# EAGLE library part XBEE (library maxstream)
XBee (TM) /XBee-PRO(TM) OEM RF Modules Source: MaxStream, Inc. xbee_productmanual.pdf
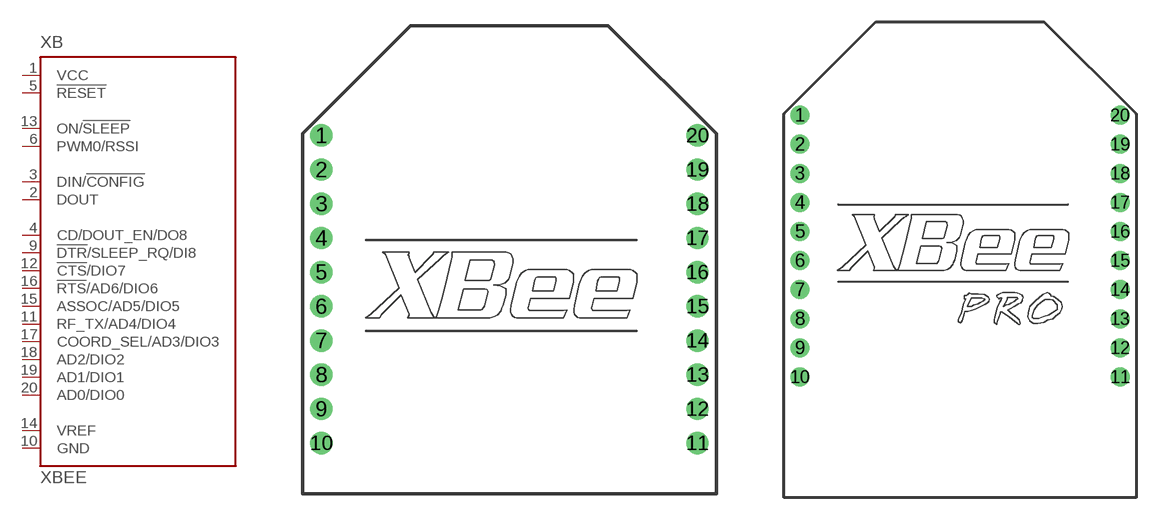
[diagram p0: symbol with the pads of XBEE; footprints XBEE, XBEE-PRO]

Designator prefix XB

## XBEE (MPN: XBP24-Z7UIT-004; OC_FARNELL: 1751799; OC_NEWARK: 34R5507)  [XBEE]
1  VCC  pwr
2  DOUT  out
3  DIN/!CONFIG  in
4  CD/DOUT_EN/DO8  out
5  !RESET  in
6  PWM0/RSSI  out
9  !DTR!/SLEEP_RQ/DI8
10  GND  pwr
11  RF_TX/AD4/DIO4
12  !CTS!/DIO7
13  ON/!SLEEP  out
14  VREF  in
15  ASSOC/AD5/DIO5
16  !RTS!/AD6/DIO6
17  COORD_SEL/AD3/DIO3
18  AD2/DIO2
19  AD1/DIO1
20  AD0/DIO0

## XBEE-PRO (MPN: XBP24-AWI-001; OC_FARNELL: 1337916; OC_NEWARK: 42M2667)  [XBEE-PRO]
Pads as for XBEE

## Footprint XBEE (pad centres in mm)
XBEE Source: http://www.maxstream.net/products/xbee/datasheet_XBee_OEM_RF-Modules.pdf
drill 0.8 pad 1.27 round: 1 -11,9; 2 -11,7; 3 -11,5; 4 -11,3; 5 -11,1; 6 -11,-1; 7 -11,-3; 8 -11,-5; 9 -11,-7; 10 -11,-9; 11 11,-9; 12 11,-7; 13 11,-5; 14 11,-3; 15 11,-1; 16 11,1; 17 11,3; 18 11,5; 19 11,7; 20 11,9

## Footprint XBEE-PRO (pad centres in mm)
XBEE Pro Source: http://www.maxstream.net/products/xbee/datasheet_XBee_OEM_RF-Modules.pdf
drill 0.8 pad 1.27 round: 1 -11,9; 2 -11,7; 3 -11,5; 4 -11,3; 5 -11,1; 6 -11,-1; 7 -11,-3; 8 -11,-5; 9 -11,-7; 10 -11,-9; 11 11,-9; 12 11,-7; 13 11,-5; 14 11,-3; 15 11,-1; 16 11,1; 17 11,3; 18 11,5; 19 11,7; 20 11,9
